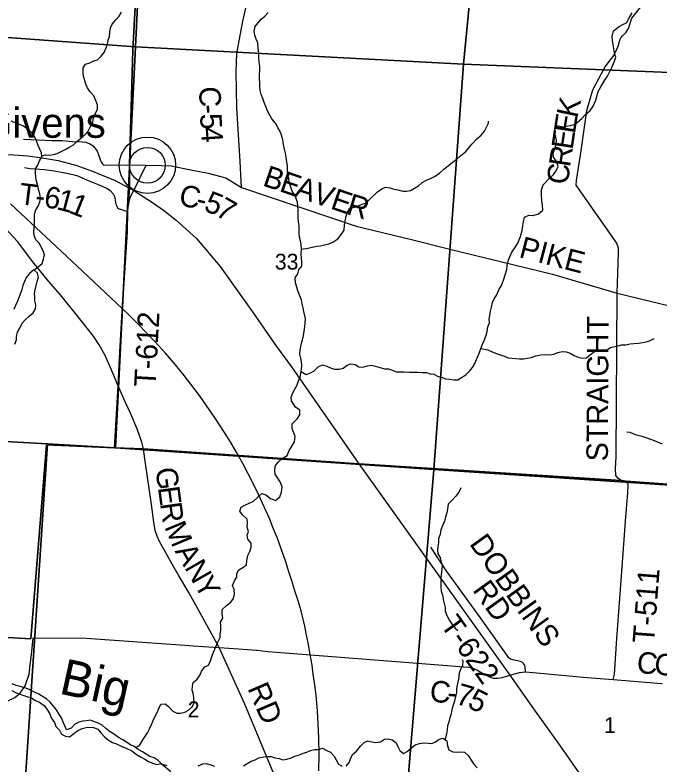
# Model space of a CAD drawing. Extents: x 1578669 to 1989827, y 208020 to 553079.
# Drawn here: x 1846121 to 1855118, y 375453 to 385917 of the extents above; entities that cross this region are included whole.
import ezdxf

# ---------------------------------------------------------------- set-up
doc = ezdxf.new("R2010")
doc.units = 0
for name, color, linetype in [('GM_X_County_Road', 7, 'Continuous'), ('GM_X_County_Road_Text', 7, 'Continuous'), ('GM_X_Minor_Lake', 7, 'Continuous'), ('GM_X_Minor_River', 7, 'Continuous'), ('GM_X_Minor_River_Text', 7, 'Continuous'), ('GM_X_Rail_Line', 7, 'Continuous'), ('GM_X_Section', 7, 'Continuous'), ('GM_X_Section_Text', 7, 'Continuous'), ('GM_X_State_Route', 7, 'Continuous'), ('GM_X_Township', 7, 'Continuous'), ('GM_X_Township_Road', 7, 'Continuous'), ('GM_X_Township_Road_Text', 7, 'Continuous'), ('GM_X_Unincorporated', 7, 'Continuous'), ('GM_X_Unincorporated_Location', 7, 'Continuous'), ('GM_X_Unincorporated_Text', 7, 'Continuous')]:
    doc.layers.add(name, color=color, linetype=linetype)

msp = doc.modelspace()

# ---------------------------------------------------------------- linework, layer by layer
at = {"layer": 'GM_X_County_Road'}
for points in [[(1849281, 383509), (1849262, 383874), (1849217, 384620), (1849206, 385125), (1849216, 385378), (1849299, 385833), (1849339, 386012)], [(1847777, 383469), (1847950, 383820)], [(1847950, 383820), (1848164, 383816), (1848299, 383814), (1848576, 383757), (1848814, 383711), (1849061, 383647), (1849281, 383509), (1850882, 382969), (1851650, 382785), (1852168, 382655), (1853617, 382299), (1854519, 382038), (1856152, 381639), (1857962, 381138), (1858648, 380880), (1858874, 380882), (1859012, 380887), (1859190, 380871), (1859390, 380853), (1859561, 380807), (1860322, 380575)], [(1847638, 380562), (1847558, 380743), (1847450, 381007), (1847372, 381177), (1847294, 381313), (1847218, 381435), (1847128, 381550), (1847041, 381660), (1846754, 382014), (1846588, 382203), (1846368, 382474), (1846158, 382756), (1846101, 382818), (1846000, 382929), (1845961, 382971), (1845888, 383032), (1845807, 383091), (1845762, 383118), (1845749, 383124)], [(1847933, 379725), (1847913, 379862), (1847891, 379956), (1847830, 380129), (1847733, 380361), (1847657, 380519), (1847638, 380562)], [(1849850, 375049), (1849325, 376303), (1848971, 377091), (1848548, 377858), (1848401, 378103), (1848314, 378257), (1848135, 378573), (1848106, 378646), (1848077, 378724), (1848059, 378840), (1848027, 379086), (1847933, 379725)], [(1846330, 376820), (1846338, 376885), (1846357, 377037), (1846377, 377229), (1847112, 377221), (1848489, 377126)], [(1848489, 377126), (1848607, 377117), (1848971, 377091)], [(1848971, 377091), (1849239, 377074), (1849491, 377054), (1849496, 377054)], [(1849496, 377054), (1849654, 377037), (1849885, 377019), (1850901, 376941), (1852210, 376835), (1852378, 376821), (1852380, 376821)], [(1845929, 376315), (1846013, 376343), (1846117, 376396), (1846194, 376457), (1846265, 376557), (1846318, 376719), (1846328, 376802), (1846330, 376820)], [(1852380, 376821), (1852449, 376816), (1852521, 376797), (1852565, 376780), (1852641, 376736), (1852740, 376681), (1852789, 376664), (1852850, 376664), (1852917, 376676), (1853023, 376708), (1853106, 376728), (1853159, 376744), (1853244, 376754), (1853397, 376738), (1854100, 376674), (1854465, 376648), (1854692, 376628), (1855137, 376589), (1855147, 376588)]]:
    msp.add_lwpolyline(points, dxfattribs=at)
at = {"layer": 'GM_X_Minor_Lake'}
msp.add_lwpolyline([(1846119, 381324), (1846141, 381383), (1846140, 381437), (1846157, 381493), (1846187, 381548), (1846221, 381616), (1846266, 381668), (1846317, 381717), (1846374, 381762), (1846406, 381817), (1846413, 381873), (1846397, 381927), (1846396, 381982), (1846395, 382032), (1846403, 382084), (1846416, 382145), (1846430, 382201), (1846449, 382259), (1846435, 382315), (1846382, 382360), (1846323, 382312), (1846277, 382253), (1846256, 382197), (1846230, 382142), (1846217, 382086), (1846187, 382009), (1846155, 381926), (1846129, 381862), (1846104, 381807)], dxfattribs=at)
at = {"layer": 'GM_X_Minor_River'}
for points in [[(1846494, 383952), (1846545, 383966), (1846599, 383961), (1846658, 383973), (1846710, 383986), (1846767, 384011), (1846830, 384047), (1846884, 384080), (1846935, 384108), (1846990, 384155), (1847046, 384200), (1847097, 384246), (1847144, 384297), (1847174, 384361), (1847205, 384426), (1847217, 384478), (1847238, 384535), (1847272, 384602), (1847274, 384662), (1847245, 384733), (1847221, 384788), (1847170, 384845), (1847134, 384900), (1847107, 384953), (1847078, 385062), (1847073, 385114), (1847071, 385178), (1847106, 385230), (1847163, 385252), (1847221, 385277), (1847274, 385293), (1847323, 385344), (1847365, 385395), (1847411, 385506), (1847421, 385564), (1847438, 385619), (1847444, 385677), (1847455, 385737), (1847477, 385791), (1847528, 385849), (1847574, 385902), (1847609, 385955)], [(1849974, 380587), (1849996, 380647), (1850031, 380704), (1850055, 380757), (1850074, 380813), (1850098, 380866), (1850109, 380922), (1850118, 380974), (1850120, 381026), (1850117, 381078), (1850106, 381128), (1850096, 381183), (1850099, 381247), (1850118, 381338), (1850140, 381422), (1850151, 381474), (1850161, 381532), (1850167, 381614), (1850173, 381684), (1850149, 381780), (1850139, 381831), (1850126, 381887), (1850116, 381943), (1850089, 382010), (1850065, 382067), (1850052, 382119), (1850032, 382182), (1850031, 382250), (1850067, 382305), (1850080, 382361), (1850120, 382412), (1850121, 382472), (1850117, 382526), (1850114, 382576), (1850116, 382650), (1850111, 382714), (1850105, 382765), (1850088, 382819), (1850087, 382869), (1850087, 382921), (1850084, 382976), (1850076, 383030), (1850069, 383088), (1850072, 383140), (1850070, 383198), (1850067, 383248), (1850063, 383303), (1850042, 383355), (1850019, 383406), (1849987, 383459), (1849970, 383513), (1849946, 383580), (1849939, 383638), (1849929, 383689), (1849924, 383755), (1849922, 383807), (1849913, 383867), (1849905, 383933), (1849892, 383988), (1849878, 384044), (1849868, 384109), (1849855, 384177), (1849839, 384242), (1849818, 384292), (1849786, 384349), (1849757, 384408), (1849705, 384467), (1849678, 384520), (1849642, 384581), (1849619, 384642), (1849597, 384696), (1849578, 384751), (1849556, 384806), (1849541, 384864), (1849535, 384922), (1849534, 384974), (1849531, 385027), (1849531, 385087), (1849534, 385143), (1849536, 385201), (1849529, 385261), (1849523, 385323), (1849520, 385377), (1849512, 385458), (1849508, 385528), (1849484, 385578), (1849465, 385635), (1849459, 385695), (1849472, 385755), (1849513, 385806), (1849553, 385857), (1849604, 385900), (1849651, 385953)], [(1853933, 384394), (1854027, 384471), (1854075, 384522), (1854142, 384583), (1854184, 384644), (1854222, 384729), (1854257, 384852), (1854291, 384917), (1854343, 385004), (1854385, 385063), (1854444, 385186), (1854482, 385275), (1854500, 385330), (1854485, 385383), (1854467, 385477), (1854456, 385562), (1854451, 385618), (1854471, 385697), (1854547, 385756), (1854599, 385786), (1854650, 385809), (1854679, 385860), (1854728, 385947)], [(1846386, 382357), (1846445, 382403), (1846498, 382452), (1846520, 382511), (1846531, 382569), (1846513, 382627), (1846484, 382680), (1846462, 382731), (1846413, 382782), (1846390, 382843), (1846386, 382893), (1846393, 383009), (1846394, 383071), (1846394, 383137), (1846414, 383199), (1846445, 383252), (1846468, 383305), (1846476, 383365), (1846467, 383420), (1846451, 383484), (1846438, 383535), (1846422, 383599), (1846411, 383651), (1846409, 383718), (1846406, 383772), (1846438, 383823), (1846461, 383884), (1846495, 383938), (1846492, 383992), (1846466, 384045), (1846445, 384095), (1846422, 384160), (1846396, 384215), (1846363, 384267), (1846312, 384315), (1846242, 384365), (1846127, 384412), (1846068, 384435)], [(1850113, 380942), (1850181, 380902), (1850243, 380925), (1850296, 380953), (1850351, 381008), (1850410, 381036), (1850470, 381019), (1850523, 380993), (1850579, 380976), (1850643, 380978), (1850697, 380991), (1850754, 381032), (1850804, 381048), (1850866, 381041), (1850919, 381007), (1850975, 381002), (1851040, 381020), (1851094, 381031), (1851150, 381017), (1851209, 380998), (1851281, 380982), (1851333, 380979), (1851386, 380963), (1851440, 380940), (1851492, 380940), (1851550, 380939), (1851622, 380935), (1851680, 380933), (1851746, 380934), (1851805, 380930), (1851859, 380929), (1851911, 380909), (1851963, 380906), (1852014, 380879), (1852074, 380863), (1852127, 380840), (1852183, 380834), (1852243, 380825), (1852297, 380829), (1852350, 380858), (1852409, 380895), (1852454, 380945), (1852503, 381000), (1852535, 381056), (1852573, 381141), (1852599, 381206), (1852618, 381264), (1852640, 381323), (1852663, 381375), (1852687, 381436), (1852708, 381502), (1852718, 381566), (1852741, 381621), (1852737, 381673), (1852746, 381725), (1852754, 381787), (1852767, 381843), (1852781, 381904), (1852804, 381956), (1852842, 382015), (1852871, 382084), (1852907, 382143), (1852933, 382217), (1852961, 382306), (1852983, 382368), (1852986, 382422), (1853004, 382503), (1853051, 382608), (1853095, 382669), (1853136, 382736), (1853173, 382827), (1853193, 382911), (1853205, 382975), (1853214, 383031), (1853230, 383096), (1853286, 383123), (1853350, 383121), (1853423, 383145), (1853484, 383194), (1853480, 383268), (1853468, 383322), (1853466, 383419), (1853464, 383479), (1853489, 383546), (1853574, 383636), (1853633, 383691), (1853669, 383744), (1853696, 383803), (1853674, 383878), (1853631, 383935), (1853627, 383991), (1853666, 384094), (1853673, 384164), (1853663, 384215), (1853652, 384273), (1853651, 384323), (1853685, 384374), (1853758, 384358), (1853811, 384365), (1853869, 384377), (1853933, 384394)], [(1850116, 382648), (1850206, 382664), (1850267, 382676), (1850329, 382691), (1850381, 382696), (1850437, 382712), (1850500, 382724), (1850554, 382749), (1850624, 382793), (1850675, 382860), (1850711, 382917), (1850715, 382989), (1850728, 383047), (1850742, 383109), (1850757, 383166), (1850785, 383222), (1850843, 383232), (1850908, 383255), (1850964, 383279), (1851019, 383296), (1851070, 383349), (1851177, 383450), (1851240, 383492), (1851290, 383513), (1851348, 383506), (1851404, 383488), (1851459, 383479), (1851529, 383457), (1851583, 383457), (1851639, 383470), (1851692, 383499), (1851749, 383533), (1851802, 383578), (1851863, 383612), (1851928, 383641), (1851980, 383669), (1852043, 383712), (1852103, 383766), (1852162, 383815), (1852219, 383861), (1852285, 383908), (1852342, 383958), (1852411, 384015), (1852453, 384066), (1852494, 384117), (1852564, 384189), (1852623, 384242), (1852671, 384298), (1852700, 384352), (1852726, 384407), (1852728, 384435)], [(1852618, 381262), (1852718, 381247), (1852777, 381217), (1852836, 381192), (1852892, 381178), (1852947, 381155), (1853001, 381136), (1853105, 381125), (1853159, 381119), (1853215, 381120), (1853271, 381131), (1853323, 381139), (1853388, 381160), (1853454, 381174), (1853518, 381182), (1853580, 381175), (1853638, 381187), (1853691, 381208), (1853755, 381222), (1853811, 381219), (1853867, 381199), (1853922, 381166), (1853975, 381142), (1854031, 381127), (1854091, 381133), (1854154, 381184), (1854205, 381223), (1854262, 381237), (1854326, 381237), (1854376, 381246), (1854429, 381277), (1854529, 381302), (1854582, 381313), (1854640, 381317), (1854700, 381330), (1854752, 381333), (1854816, 381337), (1854873, 381347), (1854923, 381358), (1854973, 381373), (1855028, 381399), (1855038, 381399)], [(1847803, 375696), (1847858, 375727), (1847890, 375782), (1847932, 375847), (1847969, 375902), (1847998, 375959), (1848026, 376017), (1848048, 376076), (1848075, 376134), (1848102, 376185), (1848126, 376242), (1848155, 376302), (1848214, 376308), (1848268, 376263), (1848321, 376203), (1848378, 376176), (1848430, 376175), (1848489, 376191), (1848539, 376216), (1848599, 376268), (1848620, 376324), (1848615, 376374), (1848609, 376436), (1848594, 376495), (1848598, 376551), (1848607, 376605), (1848662, 376651), (1848706, 376710), (1848723, 376764), (1848769, 376821), (1848822, 376847), (1848849, 376905), (1848873, 376974), (1848892, 377028), (1848922, 377103), (1848946, 377157), (1848983, 377230), (1848985, 377282), (1848994, 377336), (1848992, 377398), (1848987, 377448), (1849020, 377501), (1849010, 377562), (1849012, 377622), (1849069, 377680), (1849130, 377725), (1849170, 377776), (1849183, 377838), (1849179, 377900), (1849156, 377956), (1849184, 378022), (1849217, 378073), (1849217, 378123), (1849244, 378178), (1849299, 378207), (1849350, 378246), (1849357, 378306), (1849369, 378378), (1849395, 378431), (1849414, 378493), (1849416, 378549), (1849369, 378602), (1849360, 378658), (1849378, 378712), (1849359, 378770), (1849363, 378830), (1849360, 378882), (1849296, 378944), (1849259, 378995), (1849275, 379051), (1849329, 379076), (1849388, 379106), (1849441, 379129), (1849512, 379193), (1849566, 379240), (1849621, 379224), (1849684, 379171), (1849753, 379143), (1849816, 379195), (1849838, 379259), (1849848, 379333), (1849818, 379403), (1849789, 379454), (1849749, 379509), (1849746, 379564), (1849749, 379622), (1849793, 379680), (1849848, 379731), (1849919, 379773), (1849947, 379841), (1849978, 379894), (1850018, 379963), (1850030, 380035), (1849985, 380148), (1849985, 380214), (1850061, 380286), (1850094, 380340), (1850094, 380402), (1850033, 380445), (1849979, 380533), (1849974, 380587)], [(1855154, 379928), (1855095, 379952), (1855043, 379975), (1854992, 379994), (1854924, 380018), (1854869, 380034), (1854807, 380051), (1854751, 380067), (1854700, 380090), (1854654, 380097)], [(1852340, 379320), (1852310, 379259), (1852269, 379202), (1852213, 379143), (1852162, 379094), (1852152, 379024), (1852143, 378973), (1852125, 378917), (1852110, 378857), (1852086, 378792), (1852061, 378734), (1852053, 378669), (1852026, 378611), (1852028, 378557), (1852021, 378503), (1852013, 378451), (1852020, 378401), (1852051, 378350), (1852067, 378282), (1852078, 378227), (1852066, 378107), (1852063, 378055), (1852059, 377985), (1852060, 377935), (1852067, 377879), (1852089, 377810), (1852094, 377760), (1852121, 377651), (1852123, 377599), (1852146, 377540), (1852182, 377469), (1852219, 377414), (1852259, 377363), (1852296, 377330)], [(1852119, 375806), (1852143, 375888), (1852154, 375942), (1852158, 376002), (1852177, 376057), (1852191, 376117), (1852210, 376171), (1852218, 376227), (1852235, 376280), (1852255, 376348), (1852269, 376408), (1852282, 376463), (1852285, 376519), (1852297, 376591), (1852311, 376649), (1852323, 376739), (1852338, 376790), (1852368, 376848), (1852371, 376900), (1852362, 376920)], [(1848162, 375472), (1848117, 375516), (1848064, 375551), (1848004, 375573), (1847949, 375604), (1847898, 375635), (1847839, 375667), (1847784, 375710), (1847733, 375734), (1847626, 375805), (1847563, 375838), (1847508, 375878), (1847447, 375916), (1847389, 375963), (1847336, 376007), (1847280, 376036), (1847229, 376057), (1847173, 376077), (1847119, 376070), (1847069, 376064), (1847011, 376051), (1846956, 376024), (1846903, 375966), (1846838, 375945), (1846815, 376000), (1846793, 376051), (1846768, 376109), (1846734, 376166), (1846699, 376221), (1846653, 376277), (1846614, 376328), (1846561, 376375), (1846506, 376409), (1846455, 376442), (1846384, 376476), (1846326, 376503), (1846271, 376523), (1846211, 376542), (1846138, 376564), (1846084, 376584)], [(1846076, 376494), (1846137, 376460), (1846191, 376439), (1846244, 376421), (1846298, 376402), (1846355, 376386), (1846409, 376353), (1846462, 376330), (1846531, 376280), (1846573, 376217), (1846606, 376166), (1846628, 376109), (1846673, 376044), (1846693, 375989), (1846740, 375938), (1846770, 375885), (1846824, 375856), (1846881, 375846), (1846941, 375891), (1846992, 375929), (1847056, 375962), (1847113, 375976), (1847165, 375983), (1847217, 375974), (1847278, 375954), (1847325, 375899), (1847370, 375847), (1847420, 375804), (1847479, 375768), (1847539, 375747), (1847612, 375713), (1847671, 375689), (1847752, 375651), (1847825, 375593), (1847880, 375564), (1847933, 375532), (1847985, 375501), (1848042, 375479), (1848096, 375462), (1848162, 375472)], [(1850739, 375436), (1850781, 375487), (1850804, 375546), (1850831, 375600), (1850885, 375648), (1850941, 375717), (1850992, 375768), (1851044, 375792), (1851098, 375777), (1851156, 375767), (1851220, 375778), (1851273, 375814), (1851327, 375819), (1851383, 375802), (1851438, 375760), (1851462, 375709), (1851489, 375657), (1851540, 375615), (1851593, 375642), (1851646, 375687), (1851701, 375735), (1851762, 375752), (1851818, 375764), (1851884, 375756), (1851936, 375755), (1851986, 375774), (1852039, 375811), (1852091, 375825), (1852144, 375788), (1852153, 375721), (1852171, 375665), (1852227, 375635), (1852283, 375634), (1852339, 375635), (1852390, 375631), (1852441, 375586), (1852482, 375521), (1852522, 375464), (1852567, 375412)], [(1849307, 375443), (1849358, 375473), (1849417, 375506), (1849471, 375527), (1849524, 375551), (1849591, 375568), (1849643, 375572), (1849695, 375573), (1849746, 375554), (1849806, 375542), (1849859, 375527), (1849914, 375533), (1849972, 375552), (1850023, 375574), (1850091, 375593), (1850142, 375619), (1850194, 375634), (1850245, 375655), (1850299, 375669), (1850357, 375668), (1850410, 375687), (1850469, 375657), (1850522, 375630), (1850571, 375576), (1850603, 375523), (1850632, 375466), (1850685, 375435)], [(1848159, 375471), (1848239, 375444)], [(1848162, 375472), (1848293, 375363)], [(1848677, 375443), (1848740, 375469), (1848792, 375476), (1848852, 375457), (1848903, 375437)]]:
    msp.add_lwpolyline(points, dxfattribs=at)
at = {"layer": 'GM_X_Rail_Line'}
msp.add_lwpolyline([(1850361, 375371), (1850365, 375597), (1850361, 375834), (1850352, 376028), (1850340, 376205), (1850320, 376428), (1850299, 376602), (1850282, 376722), (1850265, 376844), (1850238, 376996), (1850209, 377158), (1850183, 377288), (1850162, 377388), (1850112, 377606), (1850072, 377744), (1850025, 377881), (1849984, 378021), (1849943, 378149), (1849893, 378301), (1849830, 378484), (1849776, 378626), (1849724, 378758), (1849670, 378891), (1849598, 379054), (1849521, 379219), (1849444, 379381), (1849374, 379517), (1849298, 379661), (1849215, 379808), (1849130, 379954), (1849044, 380093), (1848914, 380292), (1848790, 380472), (1848694, 380608), (1848574, 380767), (1848479, 380888), (1848358, 381036), (1848219, 381198), (1848067, 381366), (1847961, 381480), (1847827, 381618), (1847714, 381727), (1847614, 381821), (1847461, 381966), (1847062, 382342), (1846624, 382751), (1846059, 383281)], dxfattribs=at)
at = {"layer": 'GM_X_Section'}
for points in [[(1842456, 391746), (1848091, 391437), (1847802, 385474), (1841736, 385913)], [(1848091, 391437), (1852960, 391218), (1852375, 385230), (1847802, 385474)], [(1852960, 391218), (1858425, 390961), (1858342, 389978), (1857906, 385008), (1852375, 385230)], [(1841736, 385913), (1847802, 385474), (1847522, 379880), (1846574, 379936), (1841023, 380239), (1840799, 380252), (1841009, 383075)], [(1852375, 385230), (1851962, 379578), (1847522, 379880), (1847802, 385474)], [(1857906, 385008), (1857885, 384732), (1857433, 379214), (1851962, 379578), (1852375, 385230)], [(1846574, 379936), (1846222, 374578), (1840624, 374943), (1841023, 380239)], [(1847522, 379880), (1851962, 379578), (1851506, 374096), (1846222, 374578), (1846574, 379936)], [(1851962, 379578), (1857433, 379214), (1856997, 373846), (1856974, 373612), (1851506, 374096)]]:
    msp.add_lwpolyline(points, close=True, dxfattribs=at)
at = {"layer": 'GM_X_State_Route'}
for points in [[(1844501, 383867), (1844863, 383926), (1845039, 383940), (1845238, 383956), (1845475, 383967), (1845827, 383975), (1846104, 383966), (1846298, 383950), (1846501, 383923), (1846722, 383885), (1846843, 383856), (1846969, 383821), (1847072, 383786)], [(1847072, 383786), (1847165, 383754), (1847519, 383608), (1847717, 383501), (1847777, 383469)], [(1847777, 383469), (1848040, 383302), (1848192, 383194), (1848368, 383054), (1848652, 382798), (1848984, 382406), (1849295, 381972), (1849432, 381775), (1849769, 381293), (1849979, 381006), (1850915, 379656), (1853023, 376708), (1853353, 376235), (1853696, 375759), (1854420, 374726)]]:
    msp.add_lwpolyline(points, dxfattribs=at)
at = {"layer": 'GM_X_Township'}
for points in [[(1848332, 396849), (1848049, 390667), (1847764, 385428), (1847720, 383825), (1847717, 383501), (1847692, 383178), (1847685, 382890), (1847634, 382104), (1847578, 381136), (1847558, 380743), (1847510, 379880), (1846562, 379919), (1846344, 377214), (1840776, 377532)], [(1860929, 376281), (1859031, 376400), (1858087, 376445), (1857445, 376487), (1857181, 376481), (1857403, 379215), (1854644, 379411), (1854574, 379421), (1850915, 379656), (1847913, 379862), (1847510, 379880), (1847558, 380743), (1847578, 381136), (1847634, 382104), (1847685, 382890), (1847692, 383178), (1847717, 383501), (1847720, 383825), (1847764, 385428), (1848049, 390667), (1848332, 396849)], [(1839780, 362417), (1840250, 369801), (1840527, 374160), (1840616, 374943), (1840776, 377532), (1846344, 377214), (1846562, 379919), (1847510, 379880), (1847913, 379862), (1850915, 379656), (1854574, 379421), (1854644, 379411), (1857403, 379215), (1857181, 376481), (1857445, 376487), (1858087, 376445), (1859031, 376400), (1860929, 376281)]]:
    msp.add_lwpolyline(points, dxfattribs=at)
at = {"layer": 'GM_X_Township_Road'}
for points in [[(1854007, 383961), (1854084, 384481), (1854099, 384586), (1854182, 384871), (1854304, 385100), (1854354, 385195), (1854487, 385373), (1854494, 385389), (1854534, 385484), (1854562, 385579), (1854570, 385599), (1854594, 385625), (1854648, 385679), (1854678, 385730), (1854723, 385872), (1854867, 386054)], [(1846242, 384183), (1846637, 384167), (1846781, 384164), (1846924, 384153), (1847060, 384148), (1847109, 384141), (1847165, 384120), (1847210, 384090), (1847245, 384049), (1847268, 384017), (1847293, 383945), (1847315, 383886), (1847325, 383868)], [(1854519, 382038), (1854539, 382596), (1854537, 382666), (1854515, 382733), (1853950, 383541), (1853955, 383609), (1854007, 383961)], [(1847325, 383868), (1847336, 383846), (1847352, 383830), (1847363, 383823), (1847715, 383825)], [(1846256, 383788), (1846328, 383775), (1846534, 383763), (1846669, 383741), (1846771, 383724), (1846864, 383708), (1846908, 383698), (1846986, 383676), (1847143, 383608), (1847327, 383532), (1847414, 383491), (1847449, 383468), (1847490, 383423), (1847508, 383384), (1847513, 383362), (1847530, 383276), (1847540, 383249), (1847553, 383229), (1847567, 383217), (1847582, 383209), (1847592, 383206)], [(1847715, 383825), (1847720, 383825), (1847950, 383820)], [(1847558, 380743), (1847578, 381136), (1847634, 382104), (1847685, 382890), (1847692, 383178), (1847718, 383336), (1847743, 383404), (1847777, 383469)], [(1847592, 383206), (1847645, 383188), (1847692, 383178)], [(1854597, 379418), (1854574, 379421), (1854528, 379455), (1854502, 379494), (1854498, 379586), (1854508, 379758), (1854519, 382038)], [(1854465, 376648), (1854482, 376720), (1854515, 377218), (1854571, 377960), (1854643, 378915), (1854668, 379248), (1854674, 379342), (1854673, 379364)], [(1854673, 379364), (1854673, 379378), (1854644, 379411), (1854597, 379418)], [(1853244, 376754), (1853237, 376824), (1853217, 376864), (1853198, 376884), (1853173, 376896), (1853133, 376906), (1853090, 376914), (1853063, 376920), (1853031, 376931), (1853007, 376947), (1852615, 377505), (1852146, 378152), (1851921, 378491)]]:
    msp.add_lwpolyline(points, dxfattribs=at)
at = {"layer": 'GM_X_Unincorporated'}
for radius in [393, 249]:
    msp.add_circle((1847968, 383821), radius, dxfattribs=at)
at = {"layer": 'GM_X_Unincorporated_Location'}
msp.add_line((1847968, 383821), (1847968, 383821), dxfattribs=at)

# ---------------------------------------------------------------- texts
at = {"layer": 'GM_X_County_Road_Text'}
for s, rotation, p in [('C', 271.1671, (1848690, 384918)), ('-', 272.5227, (1848695, 384664)), ('5', 273.2864, (1848701, 384536)), ('4', 273.8044, (1848712, 384349)), ('B', 341.2318, (1849562, 383541)), ('E', 341.2289, (1849795, 383462)), ('A', 341.2317, (1850007, 383390)), ('C', 348.1121, (1848392, 383267)), ('V', 341.2305, (1850257, 383305)), ('5', 338.8422, (1848741, 383192)), ('E', 341.262, (1850507, 383220)), ('R', 342.8512, (1850729, 383145)), ('-', 346.9124, (1848631, 383217)), ('7', 330.2893, (1848902, 383130)), ('PIKE', 345.2862, (1853138, 382541)), ('G', 277.7097, (1848079, 379587)), ('E', 277.7118, (1848114, 379325)), ('R', 277.9987, (1848144, 379101)), ('M', 292.5535, (1848201, 378777)), ('A', 300.2813, (1848345, 378437)), ('N', 299.8904, (1848478, 378209)), ('Y', 299.8913, (1848609, 377980)), ('C', 354.7275, (1854784, 376740)), ('O', 354.8737, (1855030, 376718)), ('C', 355.5501, (1851899, 376336)), ('RD', 293.2633, (1849360, 376524)), ('7', 344.1447, (1852252, 376310)), ('5', 333.8166, (1852416, 376265)), ('-', 355.46, (1852144, 376317))]:
    msp.add_text(s, height=300, rotation=rotation, dxfattribs=at).set_placement(p)
at = {"layer": 'GM_X_Minor_River_Text'}
msp.add_text('Big', height=500, rotation=347.6192, dxfattribs=at).set_placement((1846722, 376453))
at = {"layer": 'GM_X_Section_Text'}
for s, p in [('33', (1849746, 382365)), ('2', (1848531, 376119)), ('1', (1854337, 375899))]:
    msp.add_text(s, height=221, rotation=0, dxfattribs=at).set_placement(p)
at = {"layer": 'GM_X_Township_Road_Text'}
for s, rotation, p in [('K', 77.762, (1853964, 384469)), ('E', 81.2965, (1853931, 384252)), ('E', 81.5311, (1853898, 384030)), ('R', 81.5862, (1853862, 383786)), ('C', 83.9275, (1853836, 383544)), ('T', 353.01, (1846167, 383279)), ('6', 350.4538, (1846513, 383239)), ('1', 345.2292, (1846688, 383210)), ('-', 353.9273, (1846395, 383251)), ('1', 338.2044, (1846857, 383165)), ('T-612', 86.913, (1848081, 380722)), ('STRAIGHT', 89.7268, (1854391, 379689)), ('DOBBINS', 305.5923, (1852450, 378539)), ('T-511', 85.5682, (1855033, 377143)), ('RD', 305.7056, (1852494, 377893)), ('T-622', 305.3747, (1852045, 377409))]:
    msp.add_text(s, height=300, rotation=rotation, dxfattribs=at).set_placement(p)
at = {"layer": 'GM_X_Unincorporated_Text'}
msp.add_text('Givens', height=417, rotation=0, dxfattribs=at).set_placement((1845652, 384204))

doc.saveas('drawing.dxf')
